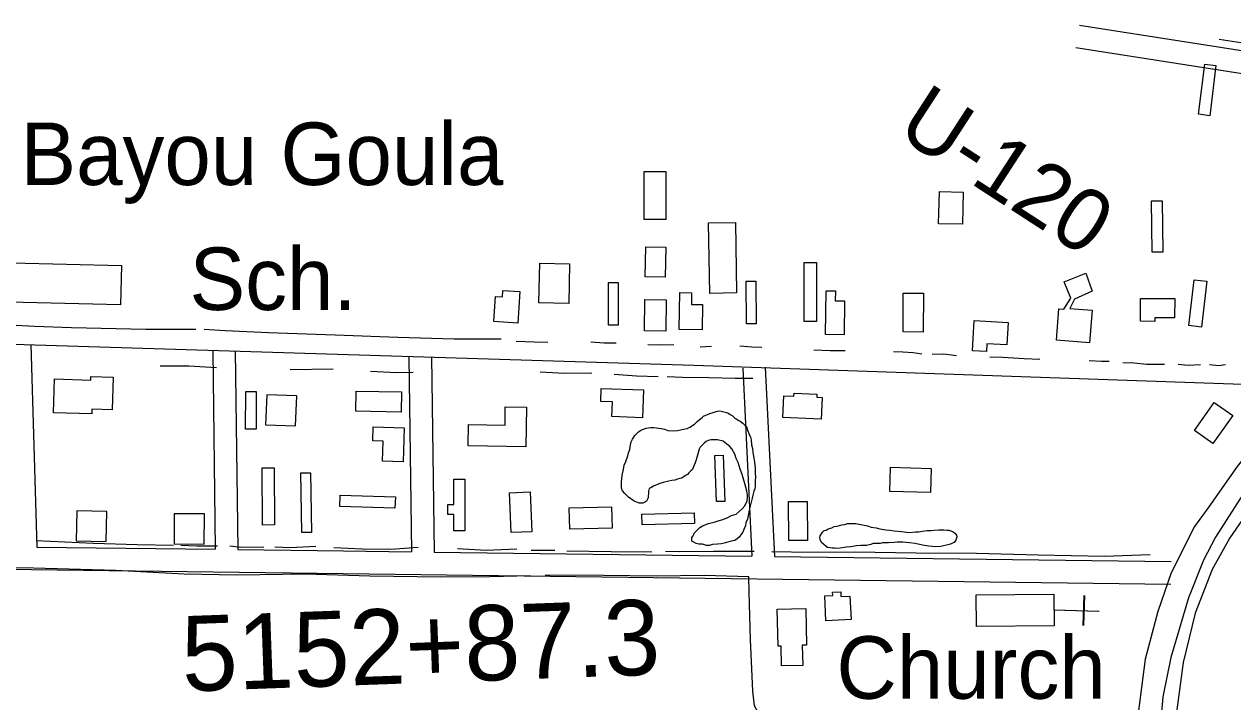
# Model space of a CAD drawing. Extents: x 3324125 to 3362000, y 600753 to 626151.
# Drawn here: x 3331027 to 3332633, y 621411 to 622311 of the extents above; entities that cross this region are included whole.
import ezdxf

# ---------------------------------------------------------------- set-up
doc = ezdxf.new("R2010")
doc.units = 0
for name, color, linetype in [('V-BLDG-IDEN', 7, 'Continuous'), ('V-BLDG-OTLN', 7, 'Continuous'), ('V-LEVE-TOET', 7, 'Continuous'), ('V-RIVR-RANG-IDEN', 7, 'Continuous'), ('V-ROAD-CNTR', 7, 'Continuous'), ('V-SITE-OTLN', 7, 'Continuous'), ('V-SITE-OTLN-IDEN', 7, 'Continuous'), ('V-SITE-VEGE', 7, 'Continuous'), ('V-SURV-IDEN', 7, 'Continuous'), ('V-TOPO-SHOR', 7, 'Continuous')]:
    doc.layers.add(name, color=color, linetype=linetype)

msp = doc.modelspace()

# ---------------------------------------------------------------- linework, layer by layer
at = {"layer": 'V-BLDG-OTLN'}
for points in [[(3332587.4, 622190.9), (3332595.7, 622257.7), (3332610.6, 622255.8), (3332602.3, 622189)], [(3331851.2, 622051.2), (3331851.2, 622115.1), (3331880, 622115.1), (3331880, 622051.2)], [(3332242.1, 622045.6), (3332243.2, 622088.3), (3332274.9, 622087.5), (3332273.8, 622044.8)], [(3331155.6, 621937.7), (3330915.1, 621943.5), (3330915.4, 621954.8), (3330894.8, 621955.3), (3330897.7, 622075.2), (3330934.6, 622074.4), (3330933, 622007.6), (3330965.2, 622006.9), (3330965.6, 622023.4), (3331011.1, 622022.3), (3331010.5, 621993.7), (3331156.9, 621990.2)], [(3332539.1, 622076), (3332540, 622007.9), (3332525.7, 622007.7), (3332524.8, 622075.8)], [(3331938.2, 621953), (3331936.6, 622046.7), (3331972.2, 622047.3), (3331973.8, 621953.6)], [(3331852.2, 621975.1), (3331853.3, 622015), (3331879.9, 622014.3), (3331878.8, 621974.4)], [(3331752, 621992.5), (3331751, 621939.6), (3331711.3, 621940.4), (3331712.3, 621993.2)], [(3332063.6, 621915.9), (3332063.5, 621994.3), (3332079.8, 621994.3), (3332079.9, 621915.9)], [(3331803.5, 621910.8), (3331803.6, 621967.4), (3331816.6, 621967.3), (3331816.6, 621910.8)], [(3331987.1, 621912.6), (3331986.7, 621969.1), (3331999.2, 621969.2), (3331999.6, 621912.7)], [(3332446, 621930.7), (3332442.6, 621887.5), (3332398.6, 621891), (3332401.9, 621932.7), (3332408.3, 621932.2), (3332417.6, 621946.7), (3332409.1, 621968.4), (3332437.8, 621979.8), (3332446.3, 621956.2), (3332422.7, 621945.4), (3332416.5, 621933)], [(3332574.6, 621910.3), (3332581.6, 621971.1), (3332598.4, 621969.1), (3332591.4, 621908.3)], [(3331683, 621913.6), (3331651.4, 621915.7), (3331653.6, 621949), (3331662.7, 621948.4), (3331663.3, 621956.9), (3331685.8, 621955.4)], [(3331897.7, 621905), (3331898.3, 621954.1), (3331914.1, 621953.9), (3331913.9, 621938.5), (3331928.6, 621938.3), (3331928.2, 621904.6)], [(3332117.2, 621943.2), (3332116.6, 621898.2), (3332091.8, 621898.5), (3332092.6, 621956.5), (3332105.1, 621956.3), (3332104.9, 621943.3)], [(3332221.9, 621953.2), (3332221.8, 621901.7), (3332194.9, 621901.8), (3332195, 621953.2)], [(3331851.4, 621903.3), (3331852, 621945), (3331880.3, 621944.6), (3331879.7, 621902.8)], [(3332510.3, 621946.4), (3332555.8, 621946.3), (3332555.7, 621920.7), (3332529.5, 621920.8), (3332529.5, 621915.9), (3332510.2, 621916)], [(3332289.4, 621917.1), (3332334.4, 621914.6), (3332332.7, 621884.7), (3332306.4, 621886.1), (3332305.8, 621875.7), (3332287.2, 621876.7)], [(3331067.9, 621839.4), (3331115.8, 621837.9), (3331115.9, 621842.8), (3331145.8, 621841.9), (3331144.4, 621798.4), (3331117.5, 621799.3), (3331117.3, 621792.9), (3331066.5, 621794.5)], [(3331335.8, 621822.6), (3331335.6, 621772.6), (3331321.6, 621772.6), (3331321.8, 621822.6)], [(3331468.5, 621823.1), (3331528.8, 621822.1), (3331528.4, 621795.4), (3331468.1, 621796.4)], [(3331794, 621826.8), (3331850.1, 621824.9), (3331848.8, 621787.9), (3331808.2, 621789.3), (3331808.9, 621808.8), (3331793.4, 621809.3)], [(3331389.6, 621817), (3331349.6, 621818.5), (3331348.2, 621778.5), (3331388.1, 621777.1)], [(3332086.3, 621786.2), (3332035.3, 621788.2), (3332036.4, 621816.9), (3332049.9, 621816.4), (3332050.1, 621820.3), (3332080.6, 621819.1), (3332080.4, 621815), (3332087.4, 621814.7)], [(3332582.1, 621770.8), (3332608.2, 621808.1), (3332632.8, 621790.8), (3332606.6, 621753.5)], [(3331693.9, 621749.1), (3331617.4, 621750.4), (3331617.9, 621779), (3331666.2, 621778.1), (3331666.6, 621802.5), (3331694.8, 621802)], [(3331491.1, 621776), (3331532.4, 621774.4), (3331530.7, 621729.4), (3331503.3, 621730.4), (3331504.3, 621756.9), (3331490.4, 621757.4)], [(3331955.9, 621738), (3331958.2, 621676.8), (3331947, 621676.4), (3331944.7, 621737.6)], [(3331344.2, 621645.3), (3331343.7, 621721.2), (3331359.5, 621721.3), (3331360.1, 621645.5)], [(3331407.8, 621714.7), (3331409.1, 621635.5), (3331396.1, 621635.3), (3331394.8, 621714.5)], [(3332178.1, 621722), (3332232.4, 621720.5), (3332231.5, 621688.4), (3332177.3, 621689.9)], [(3331612.6, 621706.4), (3331612.6, 621637.7), (3331598.2, 621637.7), (3331598.2, 621659.4), (3331590.2, 621659.4), (3331590.2, 621672.8), (3331598, 621672.8), (3331598, 621706.4)], [(3331447.2, 621685.2), (3331520.5, 621683), (3331520, 621667.8), (3331446.8, 621670.1)], [(3331699.4, 621689.4), (3331701.7, 621636.5), (3331674.4, 621635.4), (3331672.2, 621688.2)], [(3331096.5, 621624.2), (3331136.5, 621623.5), (3331137.2, 621663.5), (3331097.2, 621664.2)], [(3331751.5, 621668.4), (3331807.6, 621669.7), (3331808.3, 621641.2), (3331752.2, 621639.9)], [(3331848, 621659.8), (3331917.5, 621661.7), (3331917.9, 621647.6), (3331848.4, 621645.7)], [(3332067.6, 621676.7), (3332068, 621624.8), (3332043, 621624.6), (3332042.6, 621676.5)], [(3331226.7, 621620.2), (3331266.7, 621620.1), (3331266.8, 621660.1), (3331226.8, 621660.2)], [(3332125.8, 621519.9), (3332092.4, 621518.3), (3332090.8, 621551.3), (3332101.5, 621551.9), (3332101.3, 621556.2), (3332112.1, 621556.8), (3332112.4, 621550.4), (3332124.3, 621550.9)], [(3332292, 621552.7), (3332395.4, 621553.4), (3332395.7, 621511.3), (3332292.3, 621510.6)], [(3332027.9, 621533.6), (3332065.9, 621534.3), (3332066.8, 621485.7), (3332061.1, 621485.6), (3332061.6, 621458.8), (3332033.6, 621458.3), (3332033.1, 621484.5), (3332028.8, 621484.5)]]:
    msp.add_lwpolyline(points, close=True, dxfattribs=at)
at = {"layer": 'V-LEVE-TOET'}
msp.add_lwpolyline([(3332660.8, 621674.3), (3332629.2, 621628.5), (3332605.4, 621586.1), (3332583.1, 621528.3), (3332567, 621462.8), (3332556.7, 621386.4), (3332549.2, 621278.2), (3332541.9, 621144.3), (3332531.9, 620980.2)], dxfattribs=at)
at = {"layer": 'V-ROAD-CNTR'}
for points in [[(3334962.6, 624333), (3334881.1, 624260.2), (3334472.9, 623895.9), (3334358, 623790.3), (3334255.1, 623697.1), (3334200.7, 623647.7), (3334152.3, 623600.3), (3334077.2, 623518.6), (3333606.7, 622932.8), (3332948.8, 622115.4), (3332638.7, 621722.9), (3332601.1, 621669.5), (3332582.1, 621643.4), (3332550.9, 621581.9), (3332533.2, 621530.4), (3332516.7, 621467.3), (3332503.8, 621368.2), (3332484.7, 621134.9), (3332435.8, 620389.6)], [(3332429.2, 622309.2), (3333019, 622217.1)], [(3332424.5, 622279.5), (3333014.4, 622187.5)], [(3332722.7, 621829.2), (3331917.1, 621857.3), (3329994.2, 621916.4), (3328216, 621974)], [(3331036.2, 621885.3), (3331044.4, 621616.1)], [(3331277.9, 621876.3), (3331281.1, 621613.1)], [(3331307.9, 621876.7), (3331311.1, 621612.7)], [(3331538.4, 621868.3), (3331541.8, 621609.8)], [(3331568.4, 621868.7), (3331571.9, 621609.4)], [(3331981.9, 621853.8), (3331994.1, 621604)], [(3332011.8, 621855.2), (3332024.1, 621603.6)], [(3331044.4, 621616.1), (3331281.1, 621613.1)], [(3331311.1, 621612.7), (3331451.5, 621611), (3331541.8, 621609.8)], [(3331571.9, 621609.4), (3331994.1, 621604)], [(3332024.1, 621603.6), (3332551, 621596.8)], [(3330795.1, 621589.2), (3331451.2, 621581), (3332550.6, 621566.8)]]:
    msp.add_lwpolyline(points, dxfattribs=at)
at = {"layer": 'V-SITE-OTLN'}
for p, q in [((3332434.2, 621511.7), (3332435.5, 621551.6)), ((3332435, 621511.7), (3332436.2, 621551.7)), ((3332394.9, 621532.9), (3332454.8, 621531)), ((3332395.6, 621532.9), (3332455.6, 621531.1))]:
    msp.add_line(p, q, dxfattribs=at)
at = {"layer": 'V-SITE-VEGE'}
for points in [[(3331940.1, 621758.6), (3331937.5, 621758), (3331933.2, 621756.4), (3331930.6, 621754.3), (3331925.3, 621748.9), (3331924.3, 621746.3), (3331923.2, 621743.1), (3331921.7, 621738.3), (3331921.2, 621735.1), (3331920.1, 621731.9), (3331918.6, 621728.1), (3331915.9, 621721.8), (3331915.4, 621719.1), (3331912.8, 621717.5), (3331910.2, 621714.8), (3331908.6, 621712.7), (3331905.9, 621711.1), (3331901.2, 621707.8), (3331898.5, 621707.3), (3331895.3, 621706.2), (3331891.6, 621705.1), (3331887.9, 621704.5), (3331883.7, 621703.5), (3331876.2, 621701.8), (3331872, 621700.7), (3331863.5, 621696.9), (3331859.8, 621694.8), (3331857.7, 621693.7), (3331856.7, 621690.5), (3331856.7, 621686.8), (3331856.2, 621684.1), (3331856.2, 621681.5), (3331854.1, 621677.2), (3331851.5, 621675.1), (3331849.3, 621674.5), (3331844.5, 621674.5), (3331837.6, 621677.1), (3331830.1, 621682.3), (3331825.3, 621687.1), (3331822.1, 621690.8), (3331821, 621694.5), (3331821, 621702.5), (3331822, 621711.5), (3331823.5, 621719), (3331824.5, 621724.8), (3331826.6, 621729.6), (3331829.2, 621737.1), (3331830.3, 621741.3), (3331831.8, 621745.6), (3331832.8, 621752), (3331833.9, 621755.7), (3331835.4, 621759.4), (3331838.6, 621764.2), (3331843.3, 621769.1), (3331847.6, 621771.7), (3331850.2, 621772.8), (3331853.9, 621773.9), (3331859.8, 621775), (3331864, 621775.1), (3331873.6, 621773.5), (3331877.9, 621772.5), (3331882.6, 621770.9), (3331890.1, 621770.5), (3331895.4, 621771), (3331903.4, 621772.7), (3331908.1, 621773.8), (3331911.8, 621775.4), (3331917.7, 621779.2), (3331920.8, 621782.4), (3331924, 621785), (3331928.2, 621788.3), (3331929.8, 621789.9), (3331938.3, 621793.7), (3331948.4, 621796.4), (3331951.5, 621796.9), (3331962.2, 621794.3), (3331965.4, 621792.2), (3331968.1, 621790.7), (3331971.3, 621787.5), (3331973.4, 621786.5), (3331976.6, 621784.4), (3331978.7, 621783.3), (3331981.9, 621780.7), (3331984.6, 621778), (3331987.3, 621774.9), (3331988.4, 621771.2), (3331990.6, 621765.9), (3331992.2, 621762.2), (3331993.3, 621758.4), (3331993.8, 621752.1), (3331994.9, 621746.8), (3331995.5, 621741.5), (3331996.6, 621734), (3331997.7, 621728.7), (3331998.3, 621720.7), (3331998.4, 621714.9), (3331998.9, 621709.1), (3331998.4, 621704.3), (3331998.5, 621696.8), (3331998, 621693.6), (3331996.9, 621690.4)], [(3331996.9, 621690.4), (3331995.4, 621685.1), (3331994.4, 621680.9), (3331991.8, 621670.2), (3331990.7, 621664.9), (3331988.2, 621653.2), (3331986.1, 621648.4), (3331985.6, 621644.7), (3331983.5, 621639.3), (3331981.9, 621636.1), (3331980.3, 621633.5), (3331977.2, 621629.2), (3331974.5, 621627.1), (3331971.4, 621624.9), (3331966.6, 621623.8), (3331957.1, 621621.1), (3331953.3, 621620.5), (3331948.6, 621620), (3331941.7, 621619.4), (3331937.4, 621618.3), (3331933.7, 621618.3), (3331928.4, 621619.8), (3331923.6, 621619.8), (3331919.9, 621620.8), (3331917.2, 621622.4), (3331914.5, 621624), (3331914.5, 621628.7), (3331916.1, 621630.9), (3331917.6, 621634.6), (3331925, 621642.1), (3331928.7, 621644.3), (3331936.7, 621647.5), (3331939.9, 621648.1), (3331945.2, 621649.7), (3331949.4, 621650.8), (3331954.2, 621652.4), (3331961.1, 621655.1), (3331966.9, 621657.8), (3331973.2, 621660), (3331981.2, 621667), (3331984.9, 621670.7), (3331988, 621677.6), (3331988.5, 621681.4), (3331988.5, 621685.1), (3331987.4, 621690.4), (3331985.2, 621698.9), (3331982.5, 621707.9), (3331980.8, 621713.7), (3331978.7, 621719.5), (3331975.9, 621728.6), (3331973.2, 621733.9), (3331971.6, 621739.7), (3331967.3, 621746.6), (3331964.6, 621749.7), (3331960.9, 621752.9), (3331956.1, 621756.6), (3331948.6, 621758.7), (3331940.1, 621758.6)]]:
    msp.add_lwpolyline(points, dxfattribs=at)
msp.add_lwpolyline([(3332086.7, 621622), (3332084.6, 621626.2), (3332084.5, 621628.9), (3332085, 621631), (3332086.6, 621633.7), (3332087.7, 621635.8), (3332090.3, 621638), (3332093, 621638.5), (3332095.6, 621640.1), (3332100.4, 621641.8), (3332103.6, 621643.4), (3332107.3, 621643.9), (3332113.6, 621645.6), (3332117.4, 621646.1), (3332121.1, 621647.2), (3332132.2, 621647.3), (3332136.5, 621646.3), (3332143.4, 621645.3), (3332147.7, 621644.2), (3332152.4, 621642.7), (3332159.4, 621641.7), (3332164.2, 621640.1), (3332172.1, 621639.1), (3332177.5, 621638.6), (3332183.3, 621637.6), (3332192.3, 621636.6), (3332204, 621635.6), (3332211.5, 621636.2), (3332215.7, 621636.2), (3332220.5, 621637.3), (3332226.9, 621637.9), (3332232.2, 621637.9), (3332236.4, 621638.5), (3332242.3, 621639.1), (3332249.2, 621639.1), (3332252.9, 621638.6), (3332255.6, 621638.6), (3332258.2, 621637.6), (3332261.4, 621636.5), (3332263.6, 621634.4), (3332265.7, 621631.8), (3332266.3, 621629.7), (3332265.2, 621625.4), (3332262.6, 621622.2), (3332260.5, 621621.1), (3332257.8, 621620), (3332252.5, 621618.4), (3332248.8, 621617.9), (3332245.1, 621616.8), (3332238.2, 621616.2), (3332229.2, 621617.2), (3332220.6, 621618.7), (3332211.1, 621620.8), (3332203.6, 621621.8), (3332194.6, 621622.8), (3332187.7, 621622.7), (3332182.9, 621622.2), (3332175.4, 621621.6), (3332167.5, 621621.5), (3332164.3, 621621), (3332155.3, 621620.9), (3332152.1, 621619.3), (3332146.2, 621618.2), (3332138.8, 621618.1), (3332133, 621617.6), (3332125.5, 621616.4), (3332119.2, 621615.9), (3332111.2, 621614.7), (3332106.4, 621614.2), (3332103.8, 621614.7), (3332100.6, 621614.7), (3332097.9, 621615.2), (3332094.7, 621615.7), (3332092.6, 621616.7)], close=True, dxfattribs=at)
at = {"layer": 'V-TOPO-SHOR'}
for p, q in [((3332643.7, 622285.9), (3332614.6, 622290.2)), ((3331940.4, 621882.3), (3331925.5, 621881.8)), ((3331437.7, 621852.2), (3331381, 621851.4)), ((3331732.5, 621611.5), (3331700.8, 621611.7))]:
    msp.add_line(p, q, dxfattribs=at)
for points in [[(3332986, 622123.4), (3332943.2, 622063.5), (3332887, 621991.5), (3332833.8, 621924.8), (3332773.2, 621852.7), (3332727.4, 621796.5), (3332674.2, 621724.5), (3332642.4, 621679.5), (3332610, 621629.4), (3332593.8, 621598.7), (3332574, 621548.6), (3332550.7, 621469.4), (3332539.9, 621417.1), (3332533.7, 621346.9), (3332522.9, 621191.8), (3332508.8, 620979.1), (3332504.8, 620912)], [(3331255.7, 621905.2), (3331189.1, 621905.1), (3331090.5, 621907.3), (3331041.2, 621909.1), (3331008.7, 621910.9)], [(3331661, 621892.4), (3331598.6, 621892.3), (3331524, 621894.3), (3331440.7, 621897.4), (3331352, 621900.5), (3331294.4, 621903.4), (3331266.5, 621905.3)], [(3331723.2, 621887.8), (3331704.7, 621888.1), (3331680.9, 621889.2)], [(3331814, 621886.8), (3331798, 621887.1), (3331780, 621888.2)], [(3331890.6, 621884.9), (3331873, 621884.3), (3331855.8, 621884.6)], [(3332007.5, 621881.2), (3331994, 621881.5), (3331978.1, 621883)], [(3332118.2, 621876.6), (3332098, 621876.8), (3332076.3, 621877.5)], [(3332219.7, 621872.3), (3332208.3, 621873.9), (3332194.6, 621875), (3332182, 621875.4)], [(3332265.7, 621870.2), (3332249.3, 621872.1), (3332233.4, 621872)], [(3331283.1, 621854), (3331246, 621856.5), (3331208.1, 621856.4)], [(3332376.4, 621865.2), (3332355.9, 621866.2), (3332327.3, 621868.1), (3332310.1, 621868.4)], [(3332468.8, 621862.5), (3332458.7, 621862.4), (3332442.3, 621863.6)], [(3332542.2, 621858.5), (3332518.3, 621858.7), (3332501.8, 621860.2), (3332486.7, 621861)], [(3332589.9, 621858), (3332573.5, 621857.4), (3332560.4, 621858.6)], [(3332623.4, 621858.2), (3332614.5, 621856.9), (3332601.9, 621858.1)], [(3331544.4, 621847.9), (3331522.5, 621847.7), (3331487.3, 621849.5)], [(3331781.5, 621847.1), (3331745, 621846.8), (3331712.9, 621848.4)], [(3331869.4, 621842.3), (3331840.8, 621842.9), (3331811.3, 621845.2)], [(3331995.5, 621840.1), (3331972.1, 621840.1), (3331936.9, 621841.1), (3331902.1, 621841.3), (3331881.4, 621842.4)], [(3331225.7, 621618), (3331177.6, 621619.1), (3331119.4, 621620.9), (3331043.2, 621624.3)], [(3331284.3, 621617.3), (3331256.7, 621617.1), (3331235.4, 621618)], [(3331345.8, 621615.8), (3331315.2, 621615.6), (3331300.7, 621617.4)], [(3331415.1, 621616.7), (3331380.8, 621615), (3331360.3, 621615.9)], [(3331550.9, 621615.4), (3331514.3, 621612.9), (3331476.7, 621613.4), (3331439, 621615)], [(3331682.1, 621613.4), (3331641.1, 621611.6), (3331603.1, 621613.6)], [(3331700.1, 621577.9), (3331646, 621576.5), (3331581, 621576.1), (3331486.5, 621577.5), (3331401.1, 621580.2), (3331309.9, 621578.7), (3331239.9, 621580.3), (3331149.1, 621585), (3331039.7, 621587.9), (3330955.2, 621589.4), (3330855.7, 621592.4), (3330765.3, 621594.7), (3330678.3, 621594.9), (3330594.6, 621595.5), (3330522.1, 621597.1), (3330454.1, 621598.3), (3330411.4, 621599.2), (3330377.9, 621600.6), (3330347.5, 621600.6)], [(3331861.1, 621609.5), (3331807.4, 621609.8), (3331748.5, 621610.5)], [(3331997.2, 621610.4), (3331943.1, 621610.4), (3331897.3, 621609.7), (3331879.4, 621610)], [(3332523.3, 621605.6), (3332462.2, 621603.7), (3332374.5, 621605.3), (3332292.5, 621607.7), (3332212.3, 621607.9), (3332130.3, 621609.1), (3332072.5, 621608.7), (3332020.7, 621609.9)], [(3332480.7, 621381.5), (3332452.5, 621383.4), (3332394, 621388), (3332343.5, 621385.1), (3332284.2, 621386.8), (3332237.8, 621386), (3332155.8, 621388.7), (3332089.5, 621388.3), (3332039.8, 621387.5), (3332025.7, 621389.5), (3332010.3, 621392.3), (3332002.4, 621396.3), (3331997.4, 621405), (3331995.2, 621424.5), (3331992.2, 621493.2), (3331990.5, 621556.2), (3331989.9, 621576.5), (3331931.1, 621578.2), (3331866.9, 621577.3), (3331796.8, 621578.4), (3331719.6, 621578.9)]]:
    msp.add_lwpolyline(points, dxfattribs=at)

# ---------------------------------------------------------------- texts
at = {"layer": 'V-BLDG-IDEN'}
for s, p in [('Bayou Goula', (3331022.4, 622097)), (' Sch.', (3331216.2, 621931))]:
    msp.add_text(s, height=83, dxfattribs=at).set_placement(p)
at = {"layer": 'V-RIVR-RANG-IDEN'}
msp.add_text('U-120', height=83, rotation=327.0228, dxfattribs=at).set_placement((3332183.8, 622164.4))
at = {"layer": 'V-SITE-OTLN-IDEN'}
msp.add_text('Church', height=83, dxfattribs=at).set_placement((3332106.4, 621414.6))
at = {"layer": 'V-SURV-IDEN'}
msp.add_text('5152+87.3', height=100, rotation=2.0616, dxfattribs=at).set_placement((3331238.1, 621424.2))

doc.saveas('drawing.dxf')
